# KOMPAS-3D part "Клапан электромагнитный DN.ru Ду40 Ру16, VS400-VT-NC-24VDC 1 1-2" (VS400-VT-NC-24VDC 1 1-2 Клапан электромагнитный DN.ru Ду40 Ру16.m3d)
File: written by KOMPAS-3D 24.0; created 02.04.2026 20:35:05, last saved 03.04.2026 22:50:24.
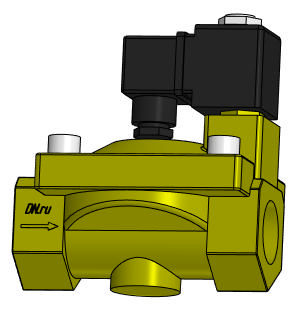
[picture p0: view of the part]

Document properties: Автор: artio; Полное имя файла: C:\Users\artio\OneDrive\Рабочий стол\Клапан электромагнитный DN.ru\VS400-VT-NC\VS400-VT-NC-24VDC 1 1-2 Клапан электромагнитный DN.ru Ду40 Ру16.m3d

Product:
- Body: Тело 1  | qty 1
    Масса: 4.144257
- Part/product: Клапан электромагнитный DN.ru Ду40 Ру16  | designation VS400-VT-NC-24VDC 1 1-2
    Масса: 2.321
    Раздел спецификации: Прочие изделия
    Примечание: D130-04737
    additional columns: ef56311e-7521-43dc-8291-0e6108b3d81d; VS400-ET-NC-220VAC 1 1-2; artio; c; Шероховатость не задана; Да

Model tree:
1. Операция без истории:1

Expressions: VS400-VT-NC-24VDC 1 1-2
